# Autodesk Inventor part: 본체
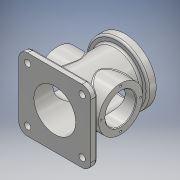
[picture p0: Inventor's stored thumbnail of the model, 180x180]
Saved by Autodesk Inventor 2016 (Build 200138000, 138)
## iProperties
Created: 2021-03
Part Number: 본체
Material: 알루미늄 6061
Document SubType Name: Modeling
Designer: Administrator
Mass: 830.73 g
Surface Area: 863.847 cm^2
Volume: 307.678 cm^3
Density: 2.7 g/cm^3
Appearance: 알루미늄 - 평지
Author: Administrator
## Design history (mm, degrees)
sketch "스케치1"
  geometry: C1 r 38 at (0, 0); 1 further point
  constraints: 1 centre point, 1 coincident
  dimensions: "d0" = 76 diameter of C1
extrude "돌출1" new body sketch "스케치1" distance "d1" = 111; taper "d2" = 0 deg
sketch "스케치2"
  geometry: L1 (-57, 57)-(57, 57); L2 (57, 57)-(57, -57); L3 (57, -57)-(-57, -57); L4 (-57, -57)-(-57, 57); L5 (-57, 57)-(57, -57); L6 (57, 57)-(-57, -57); C1 r 38 at (0, 0) reference; 1 further point
  constraints: 12 end point, 2 midpoint, 2 parallel, 1 horizontal, 1 perpendicular
  dimensions: "d3" = 114 distance of L2.end L3.end; "d4" = 114 distance of L1.end L2.end
extrude "돌출2" join sketch "스케치2" distance "d5" = 10; taper "d6" = 0 deg
sketch "스케치3"
  geometry: C1 r 33 at (0, 0); 1 further point
  constraints: 1 centre point, 1 coincident
  dimensions: "d7" = 66 diameter of C1
extrude "돌출3" cut sketch "스케치3" stored distance "d8" = 10; taper "d9" = 0 deg
sketch "스케치4"
  geometry: C1 r 33 at (0, 0) reference; C2 r 38 at (0, 0) reference; C3 r 49 at (0, 0); 1 further point
  constraints: 1 centre point, 1 coincident
  dimensions: "d10" = 98 diameter of C3
extrude "돌출4" join sketch "스케치4" distance "d11" = 13; taper "d12" = 0 deg
sketch "스케치5"
  geometry: C1 r 37 at (0, 0); 1 further point
  constraints: 1 centre point, 1 coincident
  dimensions: "d13" = 74 diameter of C1
extrude "돌출5" cut sketch "스케치5" distance "d14" = 7; taper "d15" = 0 deg
node "작업 평면1"
sketch "스케치6"
  geometry: L1 (0, -57)-(0, 57) reference; C1 r 35 at (-54, 0); 2 further points
  constraints: 1 centre point, 1 horizontal alignment, 1 midpoint
  dimensions: "d17" = 70 diameter of C1; "d18" = 54 distance from line of C1.centre L1
extrude "돌출6" join sketch "스케치6" stored distance "d19" = 7; taper "d20" = 0 deg
sketch "스케치7"
  geometry: C1 r 24 at (0, 0); C2 r 35 at (0, 0) reference; 1 further point
  constraints: 1 centre point, 1 concentric
  dimensions: "d21" = 48 diameter of C1
extrude "돌출7" cut sketch "스케치7" stored distance "d22" = 7; taper "d23" = 0 deg
sketch "스케치8" dims "d24" = 84
  geometry: 3 further points
  constraints: 2 horizontal alignment, 1 coincident, 2 other
hole "구멍1" sketch "스케치8" at (42, 0) diameter "d25" = 3.242; stored, may be unused: countersink angle "d29" = 90 deg, drill point angle "d31" = 118 deg; dims "d26" = 6, "d27" = 4, "d28" = 2, "d30" = 8
sketch "스케치9" dims "d35" = 62
  geometry: C1 r 35 at (0, 0) reference; 3 further points
  constraints: 1 vertical alignment, 3 other
hole "구멍2" sketch "스케치9" at (0, 31) diameter "d36" = 3.242; stored, may be unused: countersink angle "d40" = 90 deg, drill point angle "d42" = 118 deg; dims "d37" = 6, "d38" = 4, "d39" = 2, "d41" = 8
node "작업 평면2"
sketch "스케치10"
  geometry: L1 (0, 67)-(0, 41); L2 (-57, 0)-(57, 0) reference; L3 (-7, 54)-(8.753, 54); L4 (7, 54)-(7, 41); L5 (-7, 54)-(-7, 41); L6 (7, 70)-(7, 54); L7 (-7, 70)-(-7, 54); A1 r 7 centre (0, 41) between (-7, 41) and (7, 41); A2 r 7 centre (0, 70) between (7, 70) and (-7, 70); 6 further points
  constraints: 14 end point, 6 point on circle, 5 vertical, 3 tangent, 2 centre point, 2 midpoint, 2 point on line, 2 vertical alignment, 1 coincident
  dimensions: "d47" = 14 diameter of A1; "d49" = 54 distance from line of L2 point (0, 54); "d87" = 20 distance from line of L3 point (0, 34); "d88" = 43 distance of point (0, 34) point (0, 77); "d89" = 14 diameter of A2; "d90" = 23 vertical distance of L3.start point (0, 77)
extrude "돌출8" join sketch "스케치10" stored distance "d50" = 7; taper "d51" = 15 deg
fillet "모깎기1" dims "d52" = 14
sketch "스케치11"
  geometry: L1 (0, 80.38)-(0, -83.279) reference; L2 (80.38, 0)-(-83.279, 0) reference; C1 r 5 at (-43, -43); C2 r 5 at (-43, 43); C3 r 5 at (43, -43); C4 r 5 at (43, 43); A1 r 14 centre (-43, -43) between (-57, -43) and (-43, -57) reference; 1 further point
  constraints: 4 centre point, 3 symmetric about line, 1 concentric, 3 other
  dimensions: "d53" = 10 diameter of C1
extrude "돌출9" cut sketch "스케치11" stored distance "d54" = 7; taper "d55" = 0 deg
fillet "모깎기2" dims "d56" = 3
chamfer "모따기1" distance "d57" = 1; stored, may be unused: second distance "d58" = 2, angle "d59" = 45 deg
chamfer "모따기2" distance "d60" = 1; stored, may be unused: second distance "d61" = 2, angle "d62" = 45 deg
chamfer "모따기3" distance "d63" = 1; stored, may be unused: second distance "d64" = 2, angle "d65" = 45 deg
hole "구멍4" diameter "d80" = 4.134; stored, may be unused: countersink angle "d84" = 90 deg, drill point angle "d86" = 118 deg; dims "d78" = 10, "d79" = 10, "d81" = 8, "d82" = 4, "d83" = 2, "d85" = 10
hole "구멍5" diameter "d93" = 4.134; stored, may be unused: countersink angle "d97" = 90 deg, drill point angle "d99" = 118 deg; dims "d91" = 10, "d92" = 10, "d94" = 8, "d95" = 4, "d96" = 2, "d98" = 10
sketch "스케치12"
  geometry: C1 r 50 at (0, 0); 1 further point
  constraints: 1 centre point, 1 coincident, 1 other
  dimensions: "d100" = 100 diameter of C1
feature "엠보싱1" sketch "스케치12" dims "d101" = 0.5, "d102" = 0
node "솔리드1"
mirror "대칭1"
mirror "대칭2"
pattern_circular "원형 패턴1" dims angle "d33" = 360 deg
pattern_circular "원형 패턴2" dims angle "d44" = 360 deg
mirror "대칭3"
node "투영된 루프1"
node "투영된 루프2"
other parameters: "d46" = -55
